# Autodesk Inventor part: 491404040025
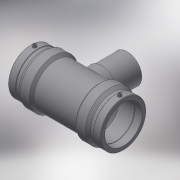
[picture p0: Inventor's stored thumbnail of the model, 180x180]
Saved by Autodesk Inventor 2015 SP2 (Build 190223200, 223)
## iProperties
Created: 2017-06
Part Number: 491404040025
Material: Generic
Description: PLASSON REDUCING TEE 40x25x40
Document SubType Name: Modeling
Designer: KIM
Mass: 149.054 g
Surface Area: 472.652 cm^2
Volume: 149.054 cm^3
Density: 1 g/cm^3
Appearance: Default
Author: KIM
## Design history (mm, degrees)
derived "491404.ipt"
feature "Solid1::491404.ipt"
tag "TaggingFeature1"
body "Solid1"
other parameters: "d2" = 56, "d3" = 43, "d4" = 24, "d5" = 50.4, "d6" = 38, "d8" = 168 deg, "d10" = 17.2, "d11" = 5.73333, "d14" = 17.6296, "d17" = 36, "d19" = 3.52592, "d20" = 168 deg, "d22" = 52.08, "d23" = 56, "d25" = 135 deg, "d26" = 84, "d29" = 47, "d30" = 15, "d31" = 48, "d34" = 5 deg, "d35" = 15, "d39" = 5 deg, "d41" = 4, "d42" = 14, "d43" = 0, "d45" = 4, "d46" = 6, "d47" = 0, "d48" = -72, "d49" = 25, "d51" = 0, "d54" = 0, "d55" = 50.4, "d56" = 56, "d57" = 42, "d58" = 135 deg, "d59" = 43, "d60" = 43, "d61" = 135 deg, "d62" = 72, "d72" = 54.6, "d73" = 27.3, "d74" = -72, "d75" = 26.25, "d77" = 0, "d80" = 0, "d81" = 25, "d82" = 44, "d83" = 0, "d84" = 3, "d85" = 0, "d86" = 14.33333, "d87" = 51.0384, "d88" = 5.73333, "d89" = 3, "d90" = 0, "L_1" = 43, "D_" = 56, "A_" = 47, "d_2" = 12, "H_" = 72, "d_1" = 25
